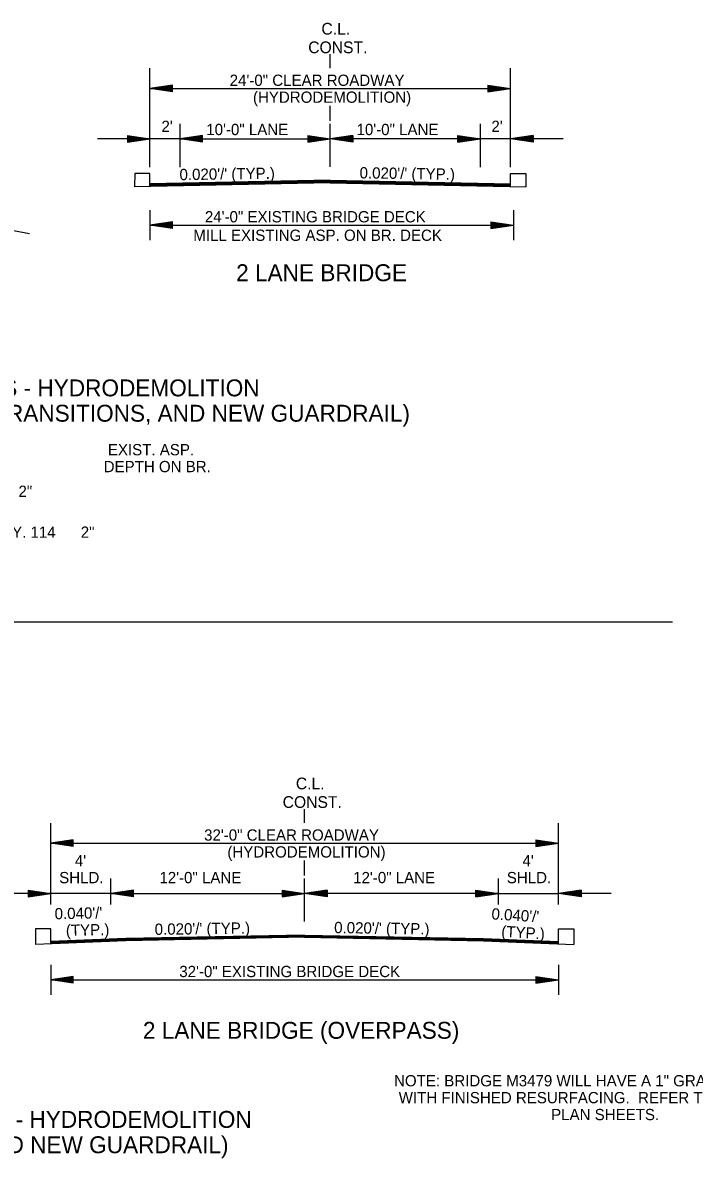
# Model space of a CAD drawing. Extents: x 544259 to 1930787, y -1961343 to 596640.
# Drawn here: x 544807 to 545254, y -1957270 to -1956514 of the extents above; entities that cross this region are included whole.
import ezdxf

# ---------------------------------------------------------------- set-up
doc = ezdxf.new("R2010")
doc.units = 0
doc.layers.add('R_Border', color=7, linetype='Continuous')
doc.layers.add('R_Draft', color=7, linetype='Continuous')

msp = doc.modelspace()

# ---------------------------------------------------------------- linework, layer by layer
at = {"layer": 'R_Border'}
for p, q in [((544911.58, -1956590.99), (544856.58, -1956590.99)), ((545166.58, -1956590.99), (545111.58, -1956590.99)), ((544881.42, -1956614.06), (544881.4, -1956622.87)), ((544891.58, -1956614.06), (544881.42, -1956614.06)), ((544891.58, -1956622.5), (544891.58, -1956614.06)), ((545131.58, -1956622.5), (545131.58, -1956614.06)), ((545131.58, -1956614.06), (545141.75, -1956614.06)), ((545141.75, -1956614.06), (545141.76, -1956622.87)), ((544317.87, -1956912.4), (545239.45, -1956912.4)), ((544825.55, -1957093.35), (544790.55, -1957093.35)), ((545198.55, -1957093.35), (545163.55, -1957093.35)), ((544825.55, -1957116.82), (544815.39, -1957116.82)), ((544815.39, -1957116.82), (544815.42, -1957127.24)), ((544825.55, -1957126.53), (544825.55, -1957116.82)), ((545163.55, -1957126.53), (545163.55, -1957116.82)), ((545163.55, -1957116.82), (545173.72, -1957116.82)), ((545173.72, -1957116.82), (545173.69, -1957127.24)), ((544875.55, -1957124.83), (544815.42, -1957127.24)), ((544875.55, -1957123.33), (544825.55, -1957125.33)), ((544875.55, -1957123.63), (544825.55, -1957125.63)), ((544875.55, -1957123.93), (544825.55, -1957125.93)), ((544875.55, -1957124.23), (544825.55, -1957126.23)), ((544875.55, -1957124.53), (544825.55, -1957126.53)), ((545113.55, -1957123.33), (545163.55, -1957125.33)), ((545113.55, -1957123.63), (545163.55, -1957125.63)), ((545113.55, -1957123.93), (545163.55, -1957125.93)), ((545113.55, -1957124.23), (545163.55, -1957126.23)), ((545113.55, -1957124.53), (545163.55, -1957126.53)), ((545113.55, -1957124.83), (545173.69, -1957127.24))]:
    msp.add_line(p, q, dxfattribs=at)
at = {"layer": 'R_Draft'}
for p, q in [((545011.58, -1956544.04), (545011.58, -1956534.73)), ((544891.58, -1956609.82), (544891.58, -1956544.08)), ((545131.58, -1956609.82), (545131.58, -1956544.08)), ((544906.58, -1956555.2), (544891.58, -1956557.45)), ((544891.58, -1956557.45), (545131.58, -1956557.45)), ((544906.58, -1956559.7), (544891.58, -1956557.45)), ((544906.58, -1956555.58), (544894.09, -1956557.45)), ((544906.58, -1956559.33), (544894.09, -1956557.45)), ((544906.58, -1956555.96), (544896.67, -1956557.45)), ((544906.58, -1956558.95), (544896.67, -1956557.45)), ((544906.58, -1956556.34), (544899.17, -1956557.45)), ((544906.58, -1956558.57), (544899.17, -1956557.45)), ((544906.58, -1956556.72), (544901.71, -1956557.45)), ((544906.58, -1956558.18), (544901.71, -1956557.45)), ((544906.58, -1956557.1), (544904.21, -1956557.45)), ((544906.58, -1956557.81), (544904.21, -1956557.45)), ((544906.58, -1956559.7), (544906.58, -1956555.2)), ((545116.58, -1956555.2), (545131.58, -1956557.45)), ((545116.58, -1956555.2), (545116.58, -1956559.7)), ((545116.58, -1956555.58), (545129.08, -1956557.45)), ((545116.58, -1956555.96), (545126.5, -1956557.45)), ((545116.58, -1956556.34), (545124, -1956557.45)), ((545116.58, -1956556.73), (545121.46, -1956557.45)), ((545116.58, -1956557.1), (545118.95, -1956557.45)), ((545116.58, -1956559.7), (545131.58, -1956557.45)), ((545116.58, -1956558.19), (545121.46, -1956557.45)), ((545116.58, -1956558.95), (545126.5, -1956557.45)), ((545116.58, -1956559.33), (545129.08, -1956557.45)), ((545116.58, -1956558.57), (545124, -1956557.45)), ((545116.58, -1956557.81), (545118.95, -1956557.45)), ((545011.58, -1956578.97), (545011.58, -1956569.1)), ((544911.58, -1956609.82), (544911.58, -1956581.1)), ((545011.58, -1956609.65), (545011.58, -1956581.1)), ((545111.58, -1956609.82), (545111.58, -1956581.1)), ((544876.58, -1956588.74), (544891.58, -1956590.99)), ((544876.58, -1956588.74), (544876.58, -1956593.24)), ((544876.58, -1956589.12), (544889.08, -1956590.99)), ((544876.58, -1956589.5), (544886.5, -1956590.99)), ((544926.58, -1956588.74), (544911.58, -1956590.99)), ((544926.58, -1956589.12), (544914.09, -1956590.99)), ((544926.58, -1956589.5), (544916.67, -1956590.99)), ((544926.58, -1956593.24), (544926.58, -1956588.74)), ((544996.58, -1956588.74), (545011.58, -1956590.99)), ((544996.58, -1956588.74), (544996.58, -1956593.24)), ((544996.58, -1956589.12), (545009.08, -1956590.99)), ((544996.58, -1956589.5), (545006.5, -1956590.99)), ((545026.58, -1956588.74), (545011.58, -1956590.99)), ((545026.58, -1956589.12), (545014.09, -1956590.99)), ((545026.58, -1956589.5), (545016.67, -1956590.99)), ((545026.58, -1956588.74), (545026.58, -1956593.24)), ((545096.58, -1956588.74), (545111.58, -1956590.99)), ((545096.58, -1956593.24), (545096.58, -1956588.74)), ((545096.58, -1956589.12), (545109.08, -1956590.99)), ((545096.58, -1956589.5), (545106.5, -1956590.99)), ((545146.58, -1956588.74), (545131.58, -1956590.99)), ((545146.58, -1956589.12), (545134.09, -1956590.99)), ((545146.58, -1956589.5), (545136.67, -1956590.99)), ((545146.58, -1956588.74), (545146.58, -1956593.24)), ((544876.58, -1956589.87), (544884, -1956590.99)), ((544876.58, -1956590.26), (544881.46, -1956590.99)), ((544876.58, -1956590.64), (544878.95, -1956590.99)), ((544876.58, -1956593.24), (544891.58, -1956590.99)), ((544876.58, -1956591.73), (544881.46, -1956590.99)), ((544876.58, -1956592.48), (544886.5, -1956590.99)), ((544876.58, -1956592.87), (544889.08, -1956590.99)), ((544876.58, -1956592.11), (544884, -1956590.99)), ((544876.58, -1956591.34), (544878.95, -1956590.99)), ((544926.58, -1956593.24), (544911.58, -1956590.99)), ((544911.58, -1956590.99), (545011.58, -1956590.99)), ((544926.58, -1956592.87), (544914.09, -1956590.99)), ((544926.58, -1956592.48), (544916.67, -1956590.99)), ((544926.58, -1956589.87), (544919.17, -1956590.99)), ((544926.58, -1956592.11), (544919.17, -1956590.99)), ((544926.58, -1956590.26), (544921.71, -1956590.99)), ((544926.58, -1956591.72), (544921.71, -1956590.99)), ((544926.58, -1956590.64), (544924.21, -1956590.99)), ((544926.58, -1956591.34), (544924.21, -1956590.99)), ((544996.58, -1956589.87), (545004, -1956590.99)), ((544996.58, -1956590.26), (545001.46, -1956590.99)), ((544996.58, -1956590.64), (544998.95, -1956590.99)), ((544996.58, -1956593.24), (545011.58, -1956590.99)), ((544996.58, -1956591.73), (545001.46, -1956590.99)), ((544996.58, -1956592.48), (545006.5, -1956590.99)), ((544996.58, -1956592.87), (545009.08, -1956590.99)), ((544996.58, -1956592.11), (545004, -1956590.99)), ((544996.58, -1956591.34), (544998.95, -1956590.99)), ((545111.58, -1956590.99), (545011.58, -1956590.99)), ((545026.58, -1956593.24), (545011.58, -1956590.99)), ((545026.58, -1956592.87), (545014.09, -1956590.99)), ((545026.58, -1956592.48), (545016.67, -1956590.99)), ((545026.58, -1956589.87), (545019.17, -1956590.99)), ((545026.58, -1956592.11), (545019.17, -1956590.99)), ((545026.58, -1956590.26), (545021.71, -1956590.99)), ((545026.58, -1956591.73), (545021.71, -1956590.99)), ((545026.58, -1956590.64), (545024.21, -1956590.99)), ((545026.58, -1956591.34), (545024.21, -1956590.99)), ((545096.58, -1956589.87), (545104, -1956590.99)), ((545096.58, -1956590.26), (545101.46, -1956590.99)), ((545096.58, -1956590.64), (545098.95, -1956590.99)), ((545096.58, -1956593.24), (545111.58, -1956590.99)), ((545096.58, -1956591.72), (545101.46, -1956590.99)), ((545096.58, -1956592.48), (545106.5, -1956590.99)), ((545096.58, -1956592.87), (545109.08, -1956590.99)), ((545096.58, -1956592.11), (545104, -1956590.99)), ((545096.58, -1956591.34), (545098.95, -1956590.99)), ((545146.58, -1956593.24), (545131.58, -1956590.99)), ((545146.58, -1956592.87), (545134.09, -1956590.99)), ((545146.58, -1956592.48), (545136.67, -1956590.99)), ((545146.58, -1956589.87), (545139.17, -1956590.99)), ((545146.58, -1956592.11), (545139.17, -1956590.99)), ((545146.58, -1956590.26), (545141.71, -1956590.99)), ((545146.58, -1956591.73), (545141.71, -1956590.99)), ((545146.58, -1956590.64), (545144.21, -1956590.99)), ((545146.58, -1956591.34), (545144.21, -1956590.99)), ((545011.58, -1956618.6), (544891.58, -1956621)), ((545011.59, -1956618.9), (544891.58, -1956621.3)), ((545011.6, -1956619.2), (544891.58, -1956621.6)), ((545011.6, -1956619.5), (544891.58, -1956621.9)), ((545011.61, -1956619.8), (544891.58, -1956622.2)), ((545011.56, -1956619.8), (545131.58, -1956622.2)), ((545011.57, -1956619.2), (545131.58, -1956621.6)), ((545011.57, -1956619.5), (545131.58, -1956621.9)), ((545011.58, -1956618.6), (545131.58, -1956621)), ((545011.58, -1956618.9), (545131.58, -1956621.3)), ((545011.62, -1956620.27), (544881.4, -1956622.87)), ((545011.61, -1956620.1), (544891.58, -1956622.5)), ((545011.55, -1956620.1), (545131.58, -1956622.5)), ((545011.55, -1956620.27), (545141.76, -1956622.87)), ((544711.23, -1956635.56), (544811.3, -1956653.94)), ((544891.58, -1956638.45), (544891.58, -1956658.45)), ((545133.58, -1956638.45), (545133.58, -1956658.45)), ((544906.58, -1956646.2), (544891.58, -1956648.45)), ((544891.58, -1956648.45), (545131.58, -1956648.45)), ((544906.58, -1956650.7), (544891.58, -1956648.45)), ((544906.58, -1956646.58), (544894.09, -1956648.45)), ((544906.58, -1956650.33), (544894.09, -1956648.45)), ((544906.58, -1956646.96), (544896.67, -1956648.45)), ((544906.58, -1956649.95), (544896.67, -1956648.45)), ((544906.58, -1956647.34), (544899.17, -1956648.45)), ((544906.58, -1956649.57), (544899.17, -1956648.45)), ((544906.58, -1956647.72), (544901.71, -1956648.45)), ((544906.58, -1956649.18), (544901.71, -1956648.45)), ((544906.58, -1956648.1), (544904.21, -1956648.45)), ((544906.58, -1956648.81), (544904.21, -1956648.45)), ((544906.58, -1956650.7), (544906.58, -1956646.2)), ((545118.58, -1956646.2), (545133.58, -1956648.45)), ((545118.58, -1956646.2), (545118.58, -1956650.7)), ((545118.58, -1956646.58), (545131.08, -1956648.45)), ((545118.58, -1956646.96), (545128.5, -1956648.45)), ((545118.58, -1956647.34), (545126, -1956648.45)), ((545118.58, -1956647.73), (545123.46, -1956648.45)), ((545118.58, -1956648.1), (545120.95, -1956648.45)), ((545118.58, -1956650.7), (545133.58, -1956648.45)), ((545118.58, -1956649.19), (545123.46, -1956648.45)), ((545118.58, -1956649.95), (545128.5, -1956648.45)), ((545118.58, -1956650.33), (545131.08, -1956648.45)), ((545118.58, -1956649.57), (545126, -1956648.45)), ((545118.58, -1956648.81), (545120.95, -1956648.45)), ((544994.55, -1957046.39), (544994.55, -1957037.09)), ((544825.55, -1957100.64), (544825.55, -1957046.44)), ((545163.55, -1957100.64), (545163.55, -1957046.44)), ((544840.55, -1957057.56), (544825.55, -1957059.81)), ((544840.55, -1957057.94), (544828.06, -1957059.81)), ((544840.55, -1957062.06), (544840.55, -1957057.56)), ((545148.55, -1957057.56), (545163.55, -1957059.81)), ((545148.55, -1957057.56), (545148.55, -1957062.06)), ((545148.55, -1957057.94), (545161.05, -1957059.81)), ((544825.55, -1957059.81), (545163.55, -1957059.81)), ((544840.55, -1957062.06), (544825.55, -1957059.81)), ((544840.55, -1957061.69), (544828.06, -1957059.81)), ((544840.55, -1957058.32), (544830.64, -1957059.81)), ((544840.55, -1957061.3), (544830.64, -1957059.81)), ((544840.55, -1957058.69), (544833.14, -1957059.81)), ((544840.55, -1957060.93), (544833.14, -1957059.81)), ((544840.55, -1957059.08), (544835.68, -1957059.81)), ((544840.55, -1957060.54), (544835.68, -1957059.81)), ((544840.55, -1957059.46), (544838.18, -1957059.81)), ((544840.55, -1957060.16), (544838.18, -1957059.81)), ((545148.55, -1957058.32), (545158.47, -1957059.81)), ((545148.55, -1957058.69), (545155.97, -1957059.81)), ((545148.55, -1957059.08), (545153.43, -1957059.81)), ((545148.55, -1957059.46), (545150.92, -1957059.81)), ((545148.55, -1957062.06), (545163.55, -1957059.81)), ((545148.55, -1957060.55), (545153.43, -1957059.81)), ((545148.55, -1957061.3), (545158.47, -1957059.81)), ((545148.55, -1957061.69), (545161.05, -1957059.81)), ((545148.55, -1957060.93), (545155.97, -1957059.81)), ((545148.55, -1957060.16), (545150.92, -1957059.81)), ((544994.55, -1957081.33), (544994.55, -1957071.46)), ((544865.55, -1957100.64), (544865.55, -1957083.45)), ((544994.55, -1957112.01), (544994.55, -1957083.45)), ((545123.55, -1957100.64), (545123.55, -1957083.45)), ((544810.55, -1957091.1), (544825.55, -1957093.35)), ((544810.55, -1957091.1), (544810.55, -1957095.6)), ((544810.55, -1957091.47), (544823.05, -1957093.35)), ((544810.55, -1957091.85), (544820.47, -1957093.35)), ((544810.55, -1957092.23), (544817.97, -1957093.35)), ((544810.55, -1957092.62), (544815.43, -1957093.35)), ((544810.55, -1957092.99), (544812.92, -1957093.35)), ((544810.55, -1957095.6), (544825.55, -1957093.35)), ((544810.55, -1957094.08), (544815.43, -1957093.35)), ((544810.55, -1957094.84), (544820.47, -1957093.35)), ((544810.55, -1957095.22), (544823.05, -1957093.35)), ((544810.55, -1957094.46), (544817.97, -1957093.35)), ((544810.55, -1957093.7), (544812.92, -1957093.35)), ((544865.55, -1957093.35), (544825.55, -1957093.35)), ((544880.55, -1957091.1), (544865.55, -1957093.35)), ((544880.55, -1957095.6), (544865.55, -1957093.35)), ((544865.55, -1957093.35), (544994.55, -1957093.35)), ((544880.55, -1957091.47), (544868.06, -1957093.35)), ((544880.55, -1957095.22), (544868.06, -1957093.35)), ((544880.55, -1957091.85), (544870.64, -1957093.35)), ((544880.55, -1957094.84), (544870.64, -1957093.35)), ((544880.55, -1957092.23), (544873.14, -1957093.35)), ((544880.55, -1957094.46), (544873.14, -1957093.35)), ((544880.55, -1957092.61), (544875.68, -1957093.35)), ((544880.55, -1957094.07), (544875.68, -1957093.35)), ((544880.55, -1957092.99), (544878.18, -1957093.35)), ((544880.55, -1957093.7), (544878.18, -1957093.35)), ((544880.55, -1957095.6), (544880.55, -1957091.1)), ((544979.55, -1957091.1), (544994.55, -1957093.35)), ((544979.55, -1957091.1), (544979.55, -1957095.6)), ((544979.55, -1957091.47), (544992.05, -1957093.35)), ((544979.55, -1957091.85), (544989.47, -1957093.35)), ((544979.55, -1957092.23), (544986.97, -1957093.35)), ((544979.55, -1957092.62), (544984.43, -1957093.35)), ((544979.55, -1957092.99), (544981.92, -1957093.35)), ((544979.55, -1957095.6), (544994.55, -1957093.35)), ((544979.55, -1957094.08), (544984.43, -1957093.35)), ((544979.55, -1957094.84), (544989.47, -1957093.35)), ((544979.55, -1957095.22), (544992.05, -1957093.35)), ((544979.55, -1957094.46), (544986.97, -1957093.35)), ((544979.55, -1957093.7), (544981.92, -1957093.35)), ((545009.55, -1957091.1), (544994.55, -1957093.35)), ((545123.55, -1957093.35), (544994.55, -1957093.35)), ((545009.55, -1957095.6), (544994.55, -1957093.35)), ((545009.55, -1957091.47), (544997.06, -1957093.35)), ((545009.55, -1957095.22), (544997.06, -1957093.35)), ((545009.55, -1957091.85), (544999.64, -1957093.35)), ((545009.55, -1957094.84), (544999.64, -1957093.35)), ((545009.55, -1957092.23), (545002.14, -1957093.35)), ((545009.55, -1957094.46), (545002.14, -1957093.35)), ((545009.55, -1957092.62), (545004.68, -1957093.35)), ((545009.55, -1957094.08), (545004.68, -1957093.35)), ((545009.55, -1957092.99), (545007.18, -1957093.35)), ((545009.55, -1957093.7), (545007.18, -1957093.35)), ((545009.55, -1957091.1), (545009.55, -1957095.6)), ((545108.55, -1957091.1), (545123.55, -1957093.35)), ((545108.55, -1957095.6), (545108.55, -1957091.1)), ((545108.55, -1957091.47), (545121.05, -1957093.35)), ((545108.55, -1957091.85), (545118.47, -1957093.35)), ((545108.55, -1957092.23), (545115.97, -1957093.35)), ((545108.55, -1957092.61), (545113.43, -1957093.35)), ((545108.55, -1957092.99), (545110.92, -1957093.35)), ((545108.55, -1957095.6), (545123.55, -1957093.35)), ((545108.55, -1957094.07), (545113.43, -1957093.35)), ((545108.55, -1957094.84), (545118.47, -1957093.35)), ((545108.55, -1957095.22), (545121.05, -1957093.35)), ((545108.55, -1957094.46), (545115.97, -1957093.35)), ((545108.55, -1957093.7), (545110.92, -1957093.35)), ((545123.55, -1957093.35), (545163.55, -1957093.35)), ((545178.55, -1957091.1), (545163.55, -1957093.35)), ((545178.55, -1957095.6), (545163.55, -1957093.35)), ((545178.55, -1957091.47), (545166.06, -1957093.35)), ((545178.55, -1957095.22), (545166.06, -1957093.35)), ((545178.55, -1957091.85), (545168.64, -1957093.35)), ((545178.55, -1957094.84), (545168.64, -1957093.35)), ((545178.55, -1957092.23), (545171.14, -1957093.35)), ((545178.55, -1957094.46), (545171.14, -1957093.35)), ((545178.55, -1957092.62), (545173.68, -1957093.35)), ((545178.55, -1957094.08), (545173.68, -1957093.35)), ((545178.55, -1957092.99), (545176.18, -1957093.35)), ((545178.55, -1957093.7), (545176.18, -1957093.35)), ((545178.55, -1957091.1), (545178.55, -1957095.6)), ((544994.55, -1957120.95), (544875.55, -1957123.33)), ((544994.56, -1957121.25), (544875.55, -1957123.63)), ((544994.57, -1957121.55), (544875.55, -1957123.93)), ((544994.57, -1957121.85), (544875.55, -1957124.23)), ((544994.58, -1957122.15), (544875.55, -1957124.53)), ((544994.58, -1957122.45), (544875.55, -1957124.83)), ((544994.52, -1957122.45), (545113.55, -1957124.83)), ((544994.53, -1957122.15), (545113.55, -1957124.53)), ((544994.54, -1957121.55), (545113.55, -1957123.93)), ((544994.54, -1957121.85), (545113.55, -1957124.23)), ((544994.55, -1957120.95), (545113.55, -1957123.33)), ((544994.55, -1957121.25), (545113.55, -1957123.63)), ((544825.55, -1957140.81), (544825.55, -1957160.81)), ((545163.55, -1957140.81), (545163.55, -1957160.81)), ((544840.55, -1957148.56), (544825.55, -1957150.81)), ((544840.55, -1957148.94), (544828.06, -1957150.81)), ((544840.55, -1957153.06), (544840.55, -1957148.56)), ((545148.55, -1957148.56), (545163.55, -1957150.81)), ((545148.55, -1957148.56), (545148.55, -1957153.06)), ((545148.55, -1957148.94), (545161.05, -1957150.81)), ((544825.55, -1957150.81), (545163.55, -1957150.81)), ((544840.55, -1957153.06), (544825.55, -1957150.81)), ((544840.55, -1957152.69), (544828.06, -1957150.81)), ((544840.55, -1957149.32), (544830.64, -1957150.81)), ((544840.55, -1957152.3), (544830.64, -1957150.81)), ((544840.55, -1957149.69), (544833.14, -1957150.81)), ((544840.55, -1957151.93), (544833.14, -1957150.81)), ((544840.55, -1957150.08), (544835.68, -1957150.81)), ((544840.55, -1957151.54), (544835.68, -1957150.81)), ((544840.55, -1957150.46), (544838.18, -1957150.81)), ((544840.55, -1957151.16), (544838.18, -1957150.81)), ((545148.55, -1957149.32), (545158.47, -1957150.81)), ((545148.55, -1957149.69), (545155.97, -1957150.81)), ((545148.55, -1957150.08), (545153.43, -1957150.81)), ((545148.55, -1957150.46), (545150.92, -1957150.81)), ((545148.55, -1957153.06), (545163.55, -1957150.81)), ((545148.55, -1957151.55), (545153.43, -1957150.81)), ((545148.55, -1957152.3), (545158.47, -1957150.81)), ((545148.55, -1957152.69), (545161.05, -1957150.81)), ((545148.55, -1957151.93), (545155.97, -1957150.81)), ((545148.55, -1957151.16), (545150.92, -1957150.81))]:
    msp.add_line(p, q, dxfattribs=at)

# ---------------------------------------------------------------- texts
for s, height, p in [('C.L.', 7.8, (545005.74, -1956521.64)), ('CONST.', 7.8, (544996.95, -1956534.01)), ('24\'-0" CLEAR ROADWAY ', 7.5, (544944.67, -1956555.78)), ('(HYDRODEMOLITION)', 7.5, (544960.15, -1956567.03)), ("2'", 7.5, (544899.24, -1956586.45)), ('10\'-0" LANE', 7.5, (544929.1, -1956588.53)), ('10\'-0" LANE', 7.5, (545029.1, -1956588.53)), ("2'", 7.5, (545118.9, -1956586.45)), ('24\'-0" EXISTING BRIDGE DECK', 7.5, (544928.14, -1956646.62)), ('MILL EXISTING ASP. ON BR. DECK', 7.5, (544920.43, -1956658.94)), ('2 LANE BRIDGE', 11.25, (544948.96, -1956685.76)), ('24 FT. CLEAR ROADWAY BRIDGES - HYDRODEMOLITION', 11.25, (544551.65, -1956762.41)), ('(BRIDGES WITH MILLING ON BR. DECKS, ROAD TRANSITIONS, AND NEW GUARDRAIL)', 11.25, (544439.46, -1956779.28)), (' EXIST. ASP. ', 7.5, (544860.78, -1956801.66)), ('DEPTH ON BR. ', 7.5, (544860.78, -1956812.91)), ('      4   - BR. NO. 02895 - HWY. 114      2"', 7.5, (544627.92, -1956829.37)), ('- BR. NO. 02896 - HWY. 114      2"', 7.5, (544700.04, -1956856.55)), ('C.L.', 7.8, (544988.71, -1957024)), ('CONST.', 7.8, (544979.92, -1957036.36)), ('32\'-0" CLEAR ROADWAY ', 7.5, (544927.64, -1957058.14)), ('(HYDRODEMOLITION)', 7.5, (544943.12, -1957069.39)), ("4'", 7.5, (544841.6, -1957075.23)), ("4'", 7.5, (545139.6, -1957075.23)), ('SHLD.', 7.5, (544831.14, -1957086.48)), ('12\'-0" LANE', 7.5, (544897.87, -1957086.48)), ('12\'-0" LANE', 7.5, (545026.87, -1957086.48)), ('SHLD.', 7.5, (545129.14, -1957086.48)), ('32\'-0" EXISTING BRIDGE DECK', 7.5, (544911.11, -1957148.98)), ('2 LANE BRIDGE (OVERPASS)', 11.25, (544886.88, -1957190.02)), ('NOTE: BRIDGE M3479 WILL HAVE A 1" GRADE RAISE', 7.5, (545054.07, -1957221.69)), ('       WITH FINISHED RESURFACING.  REFER TO BRIDGE', 7.5, (545037.68, -1957232.94)), ('32 FT. CLEAR ROADWAY BRIDGE - HYDRODEMOLITION', 11.25, (544556.41, -1957249.31)), ('PLAN SHEETS. ', 7.5, (545158.65, -1957244.19)), ('(ROADWAY TRANSITIONS AND NEW GUARDRAIL)', 11.25, (544583.65, -1957266.18))]:
    msp.add_text(s, height=height, dxfattribs=at).set_placement(p)
for s, rotation, p in [("0.020'/' (TYP.)", 0.87191, (544911.31, -1956618.55)), ("0.020'/' (TYP.)", 359.12809, (545031.08, -1956617.32)), ("0.040'/' ", 1.31838, (544828.21, -1957110.55)), ("0.040'/' ", 356.49522, (545118.77, -1957110.52)), ('(TYP.)', 1.31838, (544835.67, -1957121.63)), ("0.020'/' (TYP.)", 0.87191, (544894.78, -1957120.91)), ("0.020'/' (TYP.)", 359.12809, (545014.16, -1957119.68)), ('(TYP.)', 356.49522, (545125.28, -1957122.19))]:
    msp.add_text(s, height=7.5, rotation=rotation, dxfattribs=at).set_placement(p)

doc.saveas('drawing.dxf')
